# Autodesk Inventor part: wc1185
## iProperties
Shininess: 64.0
Length Units: 11272
Angle Units: 11279
Time Units: 11290
Mass Units: 11286
Length Display Precision: 3
Angle Display Precision: 2
Compacted: True
Part Number: wc1185
Document SubType Name: Modeling
Created: 2004-08
Designer: John Blackburn
Manufacturer: Standard
Standards Organization: Custom
Material: Aluminum-6061
Density: 0.0
Volumn: 0.0
Area: 0.0
PropertySet Name: Model Information
Control State: 0
Master: False
Checked Out: False
Author: John Blackburn
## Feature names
1. Base1
